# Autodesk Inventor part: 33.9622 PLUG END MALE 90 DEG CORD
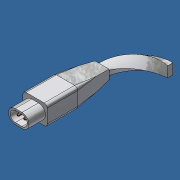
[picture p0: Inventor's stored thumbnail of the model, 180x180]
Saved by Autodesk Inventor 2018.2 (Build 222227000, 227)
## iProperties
Created: 2017-10
Part Number: 33.9622 PLUG END MALE 90 DEG CORD
Material: Generic
Document SubType Name: Modeling
Designer: Admin
Density: 1 g/cm^3
Appearance: Snow
Author: Admin
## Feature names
1. Extrusion3
2. Extrusion4
3. Fillet3
4. Extrusion8
5. Fillet4
6. Extrusion9
7. Extrusion10
8. Sweep1
## Parameters: d11 = 9.2 mm, d12 = 13.6 mm, d13 = 1.2 mm, d14 = 10.8 mm, d15 = 0, d16 = 1.5 mm, d17 = 9.4 mm, d18 = 0, d37 = 0.5 mm, d38 = 16 mm, d39 = 13 mm, d41 = 0, d42 = 2 mm, d43 = 24 mm, d44 = -8 deg, d45 = 3.3 mm, d46 = 7 mm, d47 = 0.1 mm, d48 = 0, d49 = 45 mm, d50 = 0, d51 = 90 deg
